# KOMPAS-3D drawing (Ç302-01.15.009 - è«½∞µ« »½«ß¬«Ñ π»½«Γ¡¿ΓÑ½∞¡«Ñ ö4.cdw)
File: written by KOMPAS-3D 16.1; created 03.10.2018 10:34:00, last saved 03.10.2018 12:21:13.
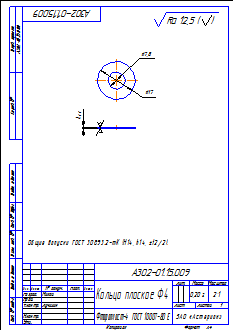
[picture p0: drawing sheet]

Sheet 1: A4, portrait

Title block, sheet 1: name: Кольцо плоское Ф4; designation: А302-01.15.009; material: Фторопласт-4  ГОСТ 10007-80 Е; mass: 0,20 г; scale: 2:1; sheets: 1; organisation: ЗАО «Астерион»; sheet format: A4; stored path: \\192.168.87.28\Konstructor_doc\Мембранные насосы\Мембранный электропривод\А302-00.00.000 - ASTRA-302 (МЭ200)\3Д ПВХ\А302-01.15.008 - Кольцо плоское уплотнительное 5-13-10 Ф4.cdw; drawn by: Милов; technical control: Лучихин

Views: Вид 1, Спереди, Проекционный вид 2
Referenced files in Z:\Мембранные насосы\Мембранный электропривод\А302-00.00.000 - ASTRA-302 (МЭ200)\3Д ПВХ\: А302-01.15.008 - Кольцо плоское Ф4.m3d, А302-01.15.009 - Кольцо плоское Ф4.m3d
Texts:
  Общие допуски ГОСТ 30893.2-mK (H14, h14,  t2/2).
  Ra 12,5
  Ra 12,5 ( )
Dimensions and other numbers on the sheet: 7,8; 17; 1; 2:1; 0,20 г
